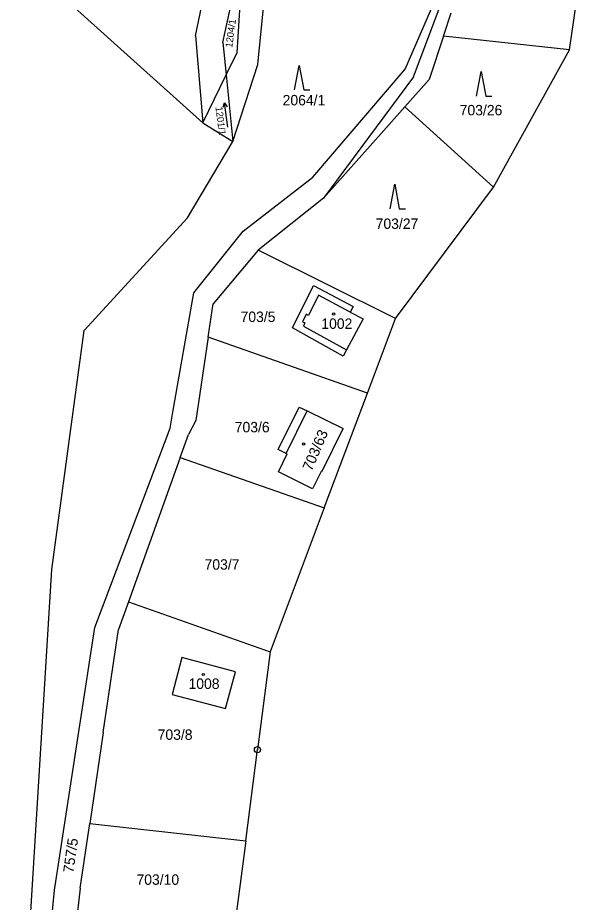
# Model space of a CAD drawing. Extents: x -779596 to -776743, y -1030330 to -1024513.
# Drawn here: x -779035.1 to -778942.2, y -1027036.5 to -1026892.1 of the extents above; entities that cross this region are included whole.
import ezdxf

# ---------------------------------------------------------------- set-up
doc = ezdxf.new("R2010")
doc.units = 0
for name, color, linetype in [('hranice parcel', 7, 'Continuous'), ('hranice vnitřní', 7, 'Continuous'), ('K_Ú_ hranice', 7, 'Continuous'), ('kultura', 7, 'Continuous'), ('Kód', 7, 'Continuous'), ('č_pacel stav_', 7, 'Continuous'), ('č_parcel poz_', 7, 'Continuous')]:
    doc.layers.add(name, color=color, linetype=linetype)

msp = doc.modelspace()

# ---------------------------------------------------------------- linework, layer by layer
at = {"layer": 'hranice parcel'}
for points in [[(-778995.99, -1026899.77), (-778990.46, -1026844.73)], [(-779006.13, -1026895.08), (-778998.08, -1026856.48)], [(-778945.16, -1026897.39), (-778942.24, -1026877.61)], [(-779001.67, -1026896.19), (-778998.24, -1026880.45)], [(-778999.35, -1026897.82), (-778998.24, -1026880.45)], [(-779032.26, -1026884.64), (-779004.92, -1026909.3)], [(-778970.59, -1026901.8), (-778965.9, -1026889.4)], [(-778965.7, -1026895.14), (-778964.46, -1026891.34)], [(-779006.13, -1026895.08), (-779004.92, -1026909.3)], [(-778965.7, -1026895.14), (-778968.02, -1026902.22)], [(-778945.16, -1026897.39), (-778965.7, -1026895.14)], [(-779001.67, -1026896.19), (-779001.13, -1026901.49)], [(-779001.13, -1026901.49), (-778999.35, -1026897.82)], [(-778957.56, -1026919.82), (-778945.16, -1026897.39)], [(-779000.03, -1026912.32), (-778995.99, -1026899.77)], [(-779004.92, -1026909.3), (-779001.13, -1026901.49)], [(-779001.13, -1026901.49), (-779000.03, -1026912.32)], [(-778970.59, -1026901.8), (-778985.25, -1026921.58)], [(-778972.01, -1026906.7), (-778968.02, -1026902.22)], [(-778972.01, -1026906.7), (-778975.85, -1026911.02)], [(-778957.56, -1026919.82), (-778972.01, -1026906.7)], [(-779004.92, -1026909.3), (-779000.03, -1026912.32)], [(-778975.85, -1026911.02), (-778985.25, -1026921.58)], [(-779007.44, -1026924.81), (-779000.03, -1026912.32)], [(-778973.5, -1026941.24), (-778957.56, -1026919.82)], [(-778985.25, -1026921.58), (-778995.9, -1026930.06)], [(-779024.27, -1026943.21), (-779007.44, -1026924.81)], [(-778995.9, -1026930.06), (-779003.25, -1026938.82)], [(-778973.5, -1026941.24), (-778995.9, -1026930.06)], [(-778990.33, -1026942.76), (-778986.88, -1026935.87)], [(-778986.88, -1026935.87), (-778980.44, -1026939.28)], [(-779004.06, -1026944.26), (-779003.25, -1026938.82)], [(-778980.44, -1026939.28), (-778980.91, -1026940.18)], [(-778978.81, -1026941.29), (-778981.49, -1026946.35)], [(-778980.91, -1026940.18), (-778978.81, -1026941.29)], [(-778978.08, -1026953.41), (-778973.5, -1026941.24)], [(-778982.03, -1026947.37), (-778990.33, -1026942.76)], [(-779029.53, -1026982.19), (-779024.27, -1026943.21)], [(-779004.06, -1026944.26), (-779006.09, -1026957.89)], [(-778978.08, -1026953.41), (-779004.06, -1026944.26)], [(-778981.49, -1026946.35), (-778982.03, -1026947.37)], [(-778985.12, -1026972.13), (-778978.08, -1026953.41)], [(-778992.63, -1026962.6), (-778989.2, -1026955.68)], [(-778989.2, -1026955.68), (-778987.91, -1026956.32)], [(-778987.91, -1026956.32), (-778982.06, -1026959.19)], [(-779006.09, -1026957.89), (-779007.27, -1026960.18)], [(-778985.49, -1026966.13), (-778982.06, -1026959.19)], [(-779008.62, -1026963.94), (-779007.27, -1026960.18)], [(-778991.33, -1026963.25), (-778992.63, -1026962.6)], [(-779008.62, -1026963.94), (-779017.07, -1026987.47)], [(-779008.62, -1026963.94), (-778985.12, -1026972.13)], [(-778992.58, -1026966.25), (-778991.18, -1026963.33)], [(-778991.18, -1026963.33), (-778991.33, -1026963.25)], [(-778987.04, -1026969.01), (-778992.58, -1026966.25)], [(-778985.6, -1026966.08), (-778987.04, -1026969.01)], [(-778985.6, -1026966.08), (-778985.49, -1026966.13)], [(-778985.12, -1026972.13), (-778993.96, -1026995.62)], [(-779035.12, -1027072.6), (-779029.53, -1026982.19)], [(-779017.07, -1026987.47), (-779018.69, -1026991.97)], [(-779017.07, -1026987.47), (-778993.96, -1026995.62)], [(-779021.17, -1027008.79), (-779018.69, -1026991.97)], [(-778993.96, -1026995.62), (-778996.02, -1027011.59)], [(-779008.34, -1026996.56), (-779009.96, -1027002.57)], [(-778999.63, -1026998.88), (-779008.34, -1026996.56)], [(-779001.22, -1027004.89), (-778999.63, -1026998.88)], [(-779009.96, -1027002.57), (-779001.22, -1027004.89)], [(-779021.17, -1027008.79), (-779023.36, -1027023.62)], [(-778997.94, -1027026.47), (-778996.02, -1027011.59)], [(-779024.93, -1027034.22), (-779023.36, -1027023.62)], [(-779023.36, -1027023.62), (-778997.94, -1027026.47)], [(-778997.94, -1027026.47), (-778999.85, -1027041.35)], [(-779024.93, -1027034.22), (-779025.41, -1027038.49)]]:
    msp.add_lwpolyline(points, dxfattribs=at)
at = {"layer": 'hranice vnitřní'}
for points in [[(-778986.06, -1026937.45), (-778987.68, -1026940.73)], [(-778980.91, -1026940.18), (-778986.06, -1026937.45)], [(-778988.08, -1026940.53), (-778988.68, -1026941.75)], [(-778987.68, -1026940.73), (-778988.08, -1026940.53)], [(-778988.68, -1026941.75), (-778988.28, -1026941.95)], [(-778988.28, -1026941.95), (-778988.54, -1026942.49)], [(-778988.54, -1026942.49), (-778981.49, -1026946.35)], [(-778991.33, -1026963.25), (-778987.91, -1026956.32)]]:
    msp.add_lwpolyline(points, dxfattribs=at)
at = {"layer": 'K_Ú_ hranice'}
for points in [[(-778971.94, -1026900.55), (-778967.12, -1026889.38)], [(-778987, -1026918.19), (-778971.94, -1026900.55)], [(-778998.37, -1026926.98), (-778987, -1026918.19)], [(-779006.4, -1026937.03), (-778998.37, -1026926.98)], [(-779009.85, -1026956.51), (-779006.4, -1026937.03)], [(-779010.26, -1026959.12), (-779009.85, -1026956.51)], [(-779022.55, -1026991.65), (-779010.26, -1026959.12)], [(-779029.12, -1027034.52), (-779022.55, -1026991.65)], [(-779032.15, -1027066.11), (-779029.12, -1027034.52)]]:
    msp.add_lwpolyline(points, dxfattribs=at)
at = {"layer": 'kultura'}
for points in [[(-778989.98, -1026903.93), (-778989.23, -1026899.93), (-778988.48, -1026903.93), (-778987.48, -1026903.93)], [(-778960.29, -1026904.94), (-778959.54, -1026900.94), (-778958.79, -1026904.94), (-778957.79, -1026904.94)], [(-779001.639, -1026906.76), (-779001.402, -1026906.05), (-779000.977, -1026906.666)], [(-779000.837, -1026910.029), (-779001.402, -1026906.05)], [(-778974.4, -1026923.32), (-778973.65, -1026919.32), (-778972.9, -1026923.32), (-778971.9, -1026923.32)]]:
    msp.add_lwpolyline(points, dxfattribs=at)
for centre in [(-778983.59, -1026940.5), (-778988.49, -1026961.71), (-779004.86, -1026999.32)]:
    msp.add_circle(centre, 0.175, dxfattribs=at)
at = {"layer": 'Kód'}
for radius in [0.5, 0.032]:
    msp.add_circle((-778996.02, -1027011.59), radius, dxfattribs=at)

# ---------------------------------------------------------------- texts
at = {"layer": 'č_pacel stav_'}
for s, p in [('1002', (-778985.61, -1026942.92)), ('1008', (-779007.266, -1027001.68))]:
    msp.add_text(s, height=1.7, dxfattribs=at).set_placement(p)
msp.add_text('703/63', height=1.7, rotation=67.00053, dxfattribs=at).set_placement((-778987.183, -1026966.245))
at = {"layer": 'č_parcel poz_'}
for s, height, rotation, p in [('1204/1', 1.14, 82.30066, (-779000.141, -1026897.086)), ('1201/1', 1.14, 277.50221, (-779002.886, -1026906.732)), ('757/5', 1.7, 81.90065, (-779026.048, -1027031.787))]:
    msp.add_text(s, height=height, rotation=rotation, dxfattribs=at).set_placement(p)
for s, p in [('2064/1', (-778991.92, -1026906.45)), ('703/26', (-778963.05, -1026908.08)), ('703/27', (-778976.75, -1026926.61)), ('703/5', (-778998.78, -1026941.8)), ('703/6', (-778999.73, -1026959.81)), ('703/7', (-779004.65, -1026982.22)), ('703/8', (-779012.3, -1027009.99)), ('703/10', (-779015.75, -1027033.65))]:
    msp.add_text(s, height=1.7, dxfattribs=at).set_placement(p)

doc.saveas('drawing.dxf')
